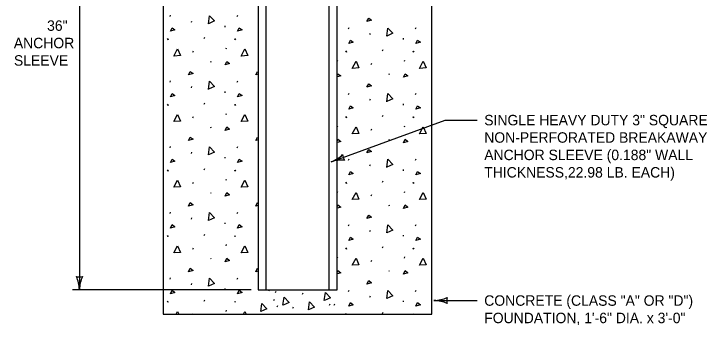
# Model space of a CAD drawing. Extents: x 49940 to 50043, y 49986 to 50011.
# Drawn here: x 49956.584 to 49960.572, y 49992.508 to 49994.296 of the extents above; entities that cross this region are included whole.
import ezdxf

# ---------------------------------------------------------------- set-up
doc = ezdxf.new("R2010")
doc.units = 0
for name, color, linetype in [('Level 1', 7, 'Continuous'), ('Level 2', 7, 'Continuous'), ('Level 3', 7, 'Continuous'), ('Level 4', 7, 'Continuous')]:
    doc.layers.add(name, color=color, linetype=linetype)

msp = doc.modelspace()

# ---------------------------------------------------------------- linework, layer by layer
at = {"layer": 'Level 1'}
for p, q in [((49957.9885, 49995.5455), (49957.9885, 49992.7114)), ((49958.443, 49992.7114), (49958.443, 49995.5455)), ((49957.4431, 49995.2975), (49957.4431, 49992.5705)), ((49958.9884, 49992.5705), (49958.9884, 49995.2975)), ((49957.4823, 49994.2807), (49957.4855, 49994.288)), ((49957.8689, 49994.2807), (49957.8723, 49994.288)), ((49957.605, 49994.2476), (49957.6082, 49994.2548)), ((49957.797, 49994.2273), (49957.7977, 49994.22)), ((49958.5086, 49994.2097), (49958.5117, 49994.217)), ((49958.8952, 49994.2097), (49958.8984, 49994.217)), ((49958.6311, 49994.1767), (49958.6345, 49994.1839)), ((49957.4653, 49994.1539), (49957.4687, 49994.1491)), ((49957.4687, 49994.1521), (49957.4718, 49994.1473)), ((49957.6785, 49994.1539), (49957.6817, 49994.1612)), ((49957.852, 49994.1539), (49957.8553, 49994.1491)), ((49957.8553, 49994.1521), (49957.8585, 49994.1473)), ((49958.8231, 49994.1564), (49958.824, 49994.1491)), ((49957.8044, 49994.0941), (49957.8076, 49994.1014)), ((49958.7046, 49994.083), (49958.7079, 49994.0903)), ((49957.613, 49994.0756), (49957.6164, 49994.0829)), ((49958.4916, 49994.083), (49958.4948, 49994.0782)), ((49958.4948, 49994.0812), (49958.498, 49994.0764)), ((49958.8782, 49994.083), (49958.8814, 49994.0782)), ((49958.8814, 49994.0812), (49958.8847, 49994.0764)), ((49957.7139, 49994.0239), (49957.7173, 49994.0191)), ((49958.4439, 49994.0232), (49958.4472, 49994.0305)), ((49958.6393, 49994.0046), (49958.6425, 49994.0118)), ((49958.8307, 49994.0232), (49958.8338, 49994.0305)), ((49958.7402, 49993.9529), (49958.7434, 49993.948)), ((49957.4823, 49993.9037), (49957.4855, 49993.9109)), ((49957.8689, 49993.9037), (49957.8723, 49993.9109)), ((49957.605, 49993.8705), (49957.6082, 49993.8778)), ((49957.797, 49993.8502), (49957.7977, 49993.8431)), ((49958.5086, 49993.8328), (49958.5117, 49993.84)), ((49958.6311, 49993.7996), (49958.6345, 49993.8068)), ((49958.8952, 49993.8328), (49958.8984, 49993.84)), ((49957.4653, 49993.7769), (49957.4687, 49993.772)), ((49957.4687, 49993.775), (49957.4718, 49993.7702)), ((49957.6785, 49993.7769), (49957.6817, 49993.7841)), ((49957.852, 49993.7769), (49957.8553, 49993.772)), ((49957.8553, 49993.775), (49957.8585, 49993.7702)), ((49958.8231, 49993.7793), (49958.824, 49993.772)), ((49957.613, 49993.6985), (49957.6164, 49993.7058)), ((49957.8044, 49993.717), (49957.8076, 49993.7243)), ((49958.4916, 49993.706), (49958.4948, 49993.7011)), ((49958.4948, 49993.7041), (49958.498, 49993.6993)), ((49958.7046, 49993.706), (49958.7079, 49993.7132)), ((49958.8782, 49993.706), (49958.8814, 49993.7011)), ((49958.8814, 49993.7041), (49958.8847, 49993.6993)), ((49957.7139, 49993.6469), (49957.7173, 49993.642)), ((49958.4439, 49993.6461), (49958.4472, 49993.6534)), ((49958.8307, 49993.6461), (49958.8338, 49993.6534)), ((49958.6393, 49993.6276), (49958.6425, 49993.6349)), ((49958.7402, 49993.576), (49958.7434, 49993.5711)), ((49957.4823, 49993.5266), (49957.4855, 49993.5338)), ((49957.8689, 49993.5266), (49957.8723, 49993.5338)), ((49957.605, 49993.4934), (49957.6082, 49993.5007)), ((49957.797, 49993.4732), (49957.7977, 49993.466)), ((49958.5086, 49993.4557), (49958.5117, 49993.4629)), ((49958.8952, 49993.4557), (49958.8984, 49993.4629)), ((49957.6785, 49993.3998), (49957.6817, 49993.407)), ((49958.6311, 49993.4225), (49958.6345, 49993.4298)), ((49957.4653, 49993.3998), (49957.4687, 49993.3949)), ((49957.4687, 49993.398), (49957.4718, 49993.3931)), ((49957.852, 49993.3998), (49957.8553, 49993.3949)), ((49957.8553, 49993.398), (49957.8585, 49993.3931)), ((49958.8231, 49993.4022), (49958.824, 49993.3949)), ((49957.613, 49993.3214), (49957.6164, 49993.3287)), ((49957.8044, 49993.3399), (49957.8076, 49993.3472)), ((49958.4916, 49993.3289), (49958.4948, 49993.324)), ((49958.4948, 49993.327), (49958.498, 49993.3222)), ((49958.7046, 49993.3289), (49958.7079, 49993.3361)), ((49958.8782, 49993.3289), (49958.8814, 49993.324)), ((49958.8814, 49993.327), (49958.8847, 49993.3222)), ((49957.7139, 49993.2698), (49957.7173, 49993.2649)), ((49958.4439, 49993.269), (49958.4472, 49993.2763)), ((49958.6393, 49993.2505), (49958.6425, 49993.2578)), ((49958.8307, 49993.269), (49958.8338, 49993.2763)), ((49958.7402, 49993.1989), (49958.7434, 49993.194)), ((49957.4823, 49993.1495), (49957.4855, 49993.1568)), ((49957.8689, 49993.1495), (49957.8723, 49993.1568)), ((49957.605, 49993.1165), (49957.6082, 49993.1236)), ((49957.797, 49993.0962), (49957.7977, 49993.0889)), ((49958.5086, 49993.0786), (49958.5117, 49993.0859)), ((49958.6311, 49993.0454), (49958.6345, 49993.0527)), ((49958.8952, 49993.0786), (49958.8984, 49993.0859)), ((49957.4653, 49993.0227), (49957.4687, 49993.0178)), ((49957.4687, 49993.0209), (49957.4718, 49993.016)), ((49957.6785, 49993.0227), (49957.6817, 49993.03)), ((49957.852, 49993.0227), (49957.8553, 49993.0178)), ((49957.8553, 49993.0209), (49957.8585, 49993.016)), ((49958.8231, 49993.0251), (49958.824, 49993.018)), ((49957.8044, 49992.9628), (49957.8076, 49992.9701)), ((49957.613, 49992.9444), (49957.6164, 49992.9516)), ((49958.4916, 49992.9518), (49958.4948, 49992.9469)), ((49958.4948, 49992.95), (49958.498, 49992.9451)), ((49958.7046, 49992.9518), (49958.7079, 49992.9591)), ((49958.8782, 49992.9518), (49958.8814, 49992.9469)), ((49958.8814, 49992.95), (49958.8847, 49992.9451)), ((49957.7139, 49992.8927), (49957.7173, 49992.8878)), ((49958.4439, 49992.8919), (49958.4472, 49992.8992)), ((49958.8307, 49992.8919), (49958.8338, 49992.8992)), ((49958.6393, 49992.8735), (49958.6425, 49992.8807)), ((49958.7402, 49992.8218), (49958.7434, 49992.8169)), ((49957.4823, 49992.7724), (49957.4855, 49992.7797)), ((49957.8689, 49992.7724), (49957.8723, 49992.7797)), ((49957.605, 49992.7394), (49957.6082, 49992.7467)), ((49957.797, 49992.7191), (49957.7977, 49992.7118)), ((49957.9885, 49992.7114), (49958.443, 49992.7114)), ((49958.0524, 49992.7047), (49958.0557, 49992.712)), ((49958.0889, 49992.6956), (49958.0922, 49992.7029)), ((49958.244, 49992.6865), (49958.2472, 49992.6938)), ((49958.5086, 49992.7015), (49958.5117, 49992.7088)), ((49958.8952, 49992.7015), (49958.8984, 49992.7088)), ((49957.6785, 49992.6458), (49957.6817, 49992.653)), ((49958.0798, 49992.6501), (49958.083, 49992.6574)), ((49958.6311, 49992.6683), (49958.6345, 49992.6756)), ((49957.4653, 49992.6458), (49957.4687, 49992.6409)), ((49957.4687, 49992.6438), (49957.4718, 49992.6389)), ((49957.852, 49992.6458), (49957.8553, 49992.6409)), ((49957.8553, 49992.6438), (49957.8585, 49992.6389)), ((49958.0981, 49992.6138), (49958.1013, 49992.6211)), ((49958.1894, 49992.6047), (49958.1925, 49992.612)), ((49958.399, 49992.6229), (49958.4024, 49992.6301)), ((49958.4264, 49992.6229), (49958.4296, 49992.6301)), ((49958.8231, 49992.6482), (49958.824, 49992.6409)), ((49957.4431, 49992.5705), (49957.9885, 49992.5705)), ((49957.6144, 49992.5705), (49957.6164, 49992.5745)), ((49957.8044, 49992.5859), (49957.8076, 49992.5932)), ((49957.9885, 49992.5705), (49958.443, 49992.5705)), ((49958.443, 49992.5705), (49958.9884, 49992.5705)), ((49958.4916, 49992.5747), (49958.4945, 49992.5705)), ((49958.4948, 49992.5729), (49958.4964, 49992.5705)), ((49958.7046, 49992.5747), (49958.7079, 49992.582)), ((49958.8782, 49992.5747), (49958.8811, 49992.5705)), ((49958.8814, 49992.5729), (49958.8831, 49992.5705))]:
    msp.add_line(p, q, dxfattribs=at)
for points in [[(49957.7032, 49994.2392), (49957.7096, 49994.2854), (49957.7385, 49994.2556), (49957.7039, 49994.2395)], [(49958.6152, 49994.2514), (49958.6249, 49994.2715), (49958.641, 49994.2594), (49958.6152, 49994.2514)], [(49957.484, 49994.1959), (49957.4937, 49994.2161), (49957.5097, 49994.2039), (49957.484, 49994.1959)], [(49957.8706, 49994.1959), (49957.8803, 49994.2161), (49957.8965, 49994.2039), (49957.8706, 49994.1959)], [(49958.7294, 49994.1683), (49958.7358, 49994.2144), (49958.7647, 49994.1845), (49958.7302, 49994.1686)], [(49958.5101, 49994.125), (49958.5198, 49994.1451), (49958.536, 49994.133), (49958.5101, 49994.125)], [(49958.8969, 49994.125), (49958.9064, 49994.1451), (49958.9226, 49994.133), (49958.8969, 49994.125)], [(49957.5041, 49994.0538), (49957.5259, 49994.095), (49957.5429, 49994.057), (49957.5049, 49994.0538)], [(49957.8907, 49994.0538), (49957.9126, 49994.095), (49957.9295, 49994.057), (49957.8917, 49994.0538)], [(49957.7988, 49994.0029), (49957.8085, 49994.023), (49957.8245, 49994.0109), (49957.7988, 49994.0029)], [(49958.5302, 49993.9829), (49958.552, 49994.0239), (49958.569, 49993.9861), (49958.5311, 49993.9829)], [(49958.917, 49993.9829), (49958.9388, 49994.0239), (49958.9556, 49993.9861), (49958.9178, 49993.9829)], [(49957.589, 49993.9452), (49957.5987, 49993.9653), (49957.6149, 49993.9533), (49957.589, 49993.9452)], [(49957.9757, 49993.9452), (49957.9854, 49993.9653), (49957.9885, 49993.963)], [(49957.9885, 49993.9493), (49957.9757, 49993.9452)], [(49958.443, 49993.9417), (49958.448, 49993.9521), (49958.464, 49993.94), (49958.443, 49993.9335)], [(49958.8249, 49993.932), (49958.8346, 49993.9521), (49958.8508, 49993.94), (49958.8249, 49993.932)], [(49957.7032, 49993.8621), (49957.7096, 49993.9084), (49957.7385, 49993.8785), (49957.7039, 49993.8624)], [(49958.6152, 49993.8743), (49958.6249, 49993.8944), (49958.641, 49993.8823), (49958.6152, 49993.8743)], [(49957.484, 49993.8188), (49957.4937, 49993.8391), (49957.5097, 49993.827), (49957.484, 49993.8188)], [(49957.8706, 49993.8188), (49957.8803, 49993.8391), (49957.8965, 49993.827), (49957.8706, 49993.8188)], [(49958.7294, 49993.7912), (49958.7358, 49993.8375), (49958.7647, 49993.8075), (49958.7302, 49993.7915)], [(49958.5101, 49993.7479), (49958.5198, 49993.7681), (49958.536, 49993.7559), (49958.5101, 49993.7479)], [(49958.8969, 49993.7479), (49958.9064, 49993.7681), (49958.9226, 49993.7559), (49958.8969, 49993.7479)], [(49957.5041, 49993.6767), (49957.5259, 49993.7179), (49957.5429, 49993.6799), (49957.5049, 49993.6767)], [(49957.8907, 49993.6767), (49957.9126, 49993.7179), (49957.9295, 49993.6799), (49957.8917, 49993.6767)], [(49957.7988, 49993.6258), (49957.8085, 49993.646), (49957.8245, 49993.6338), (49957.7988, 49993.6258)], [(49958.5302, 49993.6058), (49958.552, 49993.6469), (49958.569, 49993.609), (49958.5311, 49993.6058)], [(49958.917, 49993.6058), (49958.9388, 49993.6469), (49958.9556, 49993.609), (49958.9178, 49993.6058)], [(49957.589, 49993.5681), (49957.5987, 49993.5884), (49957.6149, 49993.5763), (49957.589, 49993.5681)], [(49957.9757, 49993.5681), (49957.9854, 49993.5884), (49957.9885, 49993.586)], [(49957.9885, 49993.5722), (49957.9757, 49993.5681)], [(49958.443, 49993.5646), (49958.448, 49993.5751), (49958.464, 49993.5629), (49958.443, 49993.5564)], [(49958.8249, 49993.5549), (49958.8346, 49993.5751), (49958.8508, 49993.5629), (49958.8249, 49993.5549)], [(49957.7032, 49993.4851), (49957.7096, 49993.5313), (49957.7385, 49993.5014), (49957.7039, 49993.4854)], [(49958.6152, 49993.4972), (49958.6249, 49993.5173), (49958.641, 49993.5052), (49958.6152, 49993.4972)], [(49957.484, 49993.4417), (49957.4937, 49993.462), (49957.5097, 49993.4499), (49957.484, 49993.4417)], [(49957.8706, 49993.4417), (49957.8803, 49993.462), (49957.8965, 49993.4499), (49957.8706, 49993.4417)], [(49958.7294, 49993.4142), (49958.7358, 49993.4604), (49958.7647, 49993.4305), (49958.7302, 49993.4145)], [(49958.5101, 49993.3708), (49958.5198, 49993.391), (49958.536, 49993.3789), (49958.5101, 49993.3708)], [(49958.8969, 49993.3708), (49958.9064, 49993.391), (49958.9226, 49993.3789), (49958.8969, 49993.3708)], [(49957.5041, 49993.2996), (49957.5259, 49993.3408), (49957.5429, 49993.3028), (49957.5049, 49993.2996)], [(49957.8907, 49993.2996), (49957.9126, 49993.3408), (49957.9295, 49993.3028), (49957.8917, 49993.2996)], [(49957.7988, 49993.2487), (49957.8085, 49993.269), (49957.8245, 49993.2569), (49957.7988, 49993.2487)], [(49958.5302, 49993.2287), (49958.552, 49993.2699), (49958.569, 49993.2319), (49958.5311, 49993.2287)], [(49958.917, 49993.2287), (49958.9388, 49993.2699), (49958.9556, 49993.2319), (49958.9178, 49993.2287)], [(49957.589, 49993.191), (49957.5987, 49993.2113), (49957.6149, 49993.1992), (49957.589, 49993.191)], [(49957.9757, 49993.191), (49957.9854, 49993.2113), (49957.9885, 49993.209)], [(49957.9885, 49993.1951), (49957.9757, 49993.191)], [(49958.443, 49993.1875), (49958.448, 49993.198), (49958.464, 49993.1859), (49958.443, 49993.1793)], [(49958.8249, 49993.1778), (49958.8346, 49993.198), (49958.8508, 49993.1859), (49958.8249, 49993.1778)], [(49957.7032, 49993.108), (49957.7096, 49993.1542), (49957.7385, 49993.1243), (49957.7039, 49993.1083)], [(49958.6152, 49993.1201), (49958.6249, 49993.1402), (49958.641, 49993.1283), (49958.6152, 49993.1201)], [(49957.484, 49993.0648), (49957.4937, 49993.085), (49957.5097, 49993.0728), (49957.484, 49993.0648)], [(49957.8706, 49993.0648), (49957.8803, 49993.085), (49957.8965, 49993.0728), (49957.8706, 49993.0648)], [(49958.7294, 49993.0371), (49958.7358, 49993.0833), (49958.7647, 49993.0534), (49958.7302, 49993.0374)], [(49958.5101, 49992.9937), (49958.5198, 49993.014), (49958.536, 49993.0019), (49958.5101, 49992.9937)], [(49958.8969, 49992.9937), (49958.9064, 49993.014), (49958.9226, 49993.0019), (49958.8969, 49992.9937)], [(49957.5041, 49992.9225), (49957.5259, 49992.9638), (49957.5429, 49992.9257), (49957.5049, 49992.9225)], [(49957.8907, 49992.9225), (49957.9126, 49992.9638), (49957.9295, 49992.9257), (49957.8917, 49992.9225)], [(49957.7988, 49992.8716), (49957.8085, 49992.8919), (49957.8245, 49992.8798), (49957.7988, 49992.8716)], [(49958.5302, 49992.8516), (49958.552, 49992.8928), (49958.569, 49992.8548), (49958.5311, 49992.8516)], [(49958.917, 49992.8516), (49958.9388, 49992.8928), (49958.9556, 49992.8548), (49958.9178, 49992.8516)], [(49957.589, 49992.8141), (49957.5987, 49992.8342), (49957.6149, 49992.8221), (49957.589, 49992.8141)], [(49957.9757, 49992.8141), (49957.9854, 49992.8342), (49957.9885, 49992.8319)], [(49957.9885, 49992.818), (49957.9757, 49992.8141)], [(49958.443, 49992.8106), (49958.448, 49992.8209), (49958.464, 49992.8089), (49958.443, 49992.8023)], [(49958.8249, 49992.8007), (49958.8346, 49992.8209), (49958.8508, 49992.8089), (49958.8249, 49992.8007)], [(49957.7032, 49992.7309), (49957.7096, 49992.7771), (49957.7385, 49992.7473), (49957.7039, 49992.7312)], [(49958.6152, 49992.743), (49958.6249, 49992.7633), (49958.641, 49992.7512), (49958.6152, 49992.743)], [(49957.484, 49992.6877), (49957.4937, 49992.7079), (49957.5097, 49992.6957), (49957.484, 49992.6877)], [(49957.8706, 49992.6877), (49957.8803, 49992.7079), (49957.8965, 49992.6957), (49957.8706, 49992.6877)], [(49958.3692, 49992.6492), (49958.3755, 49992.6953), (49958.4045, 49992.6654), (49958.3699, 49992.6494)], [(49958.7294, 49992.66), (49958.7358, 49992.7062), (49958.7647, 49992.6764), (49958.7302, 49992.6603)], [(49958.1319, 49992.622), (49958.1383, 49992.668), (49958.1672, 49992.6382), (49958.1327, 49992.6221)], [(49958.0042, 49992.5856), (49958.0106, 49992.6317), (49958.0395, 49992.6018), (49958.005, 49992.5859)], [(49958.2778, 49992.5947), (49958.2843, 49992.6408), (49958.3131, 49992.6109), (49958.2786, 49992.595)], [(49958.5101, 49992.6167), (49958.5198, 49992.637), (49958.536, 49992.6248), (49958.5101, 49992.6167)], [(49958.8969, 49992.6167), (49958.9064, 49992.637), (49958.9226, 49992.6248), (49958.8969, 49992.6167)], [(49957.5173, 49992.5705), (49957.5259, 49992.5867), (49957.5332, 49992.5705)], [(49957.9039, 49992.5705), (49957.9126, 49992.5867), (49957.9198, 49992.5705)]]:
    msp.add_lwpolyline(points, dxfattribs=at)
at = {"layer": 'Level 3'}
for p, q in [((49956.9607, 49995.5455), (49956.9607, 49992.7114)), ((49958.4095, 49993.4457), (49959.0652, 49993.6856)), ((49959.0652, 49993.6856), (49959.2497, 49993.6856)), ((49957.9485, 49992.7114), (49956.9207, 49992.7114)), ((49959.0006, 49992.649), (49959.2497, 49992.649))]:
    msp.add_line(p, q, dxfattribs=at)
for centre, radius, start, end in [((49958.3187, 49993.6603), 0.233, 292.9301, 312.1799), ((49958.5299, 49993.4898), 0.0548, 182.2416, 217.964), ((49958.4773, 49993.234), 0.2223, 87.5588, 107.7423), ((49956.9607, 49992.8396), 0.0548, 252.1388, 287.8612), ((49956.728, 49992.6999), 0.233, 2.8273, 22.0772), ((49957.1828, 49992.7023), 0.2223, 157.456, 177.6395), ((49958.9891, 49992.8817), 0.233, 272.8273, 292.0772), ((49958.9915, 49992.4269), 0.2223, 67.456, 87.6395), ((49959.1288, 49992.649), 0.0548, 162.1388, 197.8612)]:
    msp.add_arc(centre, radius, start, end, dxfattribs=at)
at = {"layer": 'Level 4'}
for p, q in [((49958.0345, 49992.7114), (49958.0345, 49995.5455)), ((49958.3981, 49992.7114), (49958.3981, 49995.5455))]:
    msp.add_line(p, q, dxfattribs=at)

# ---------------------------------------------------------------- texts
at = {"layer": 'Level 2'}
for s, p in [('36"', (49956.7747, 49994.1984)), ('ANCHOR', (49956.5834, 49994.0984)), ('SLEEVE', (49956.5839, 49993.9984)), ('SINGLE HEAVY DUTY 3" SQUARE', (49959.2897, 49993.6556)), ('NON-PERFORATED BREAKAWAY', (49959.2897, 49993.5556)), ('ANCHOR SLEEVE (0.188" WALL ', (49959.2897, 49993.4556)), ('THICKNESS,22.98 LB. EACH)', (49959.2897, 49993.3556)), ('CONCRETE (CLASS "A" OR "D")', (49959.2897, 49992.619)), ('FOUNDATION, 1\'-6" DIA. x 3\'-0"', (49959.2897, 49992.519))]:
    msp.add_text(s, height=0.06, dxfattribs=at).set_placement(p)

doc.saveas('drawing.dxf')
